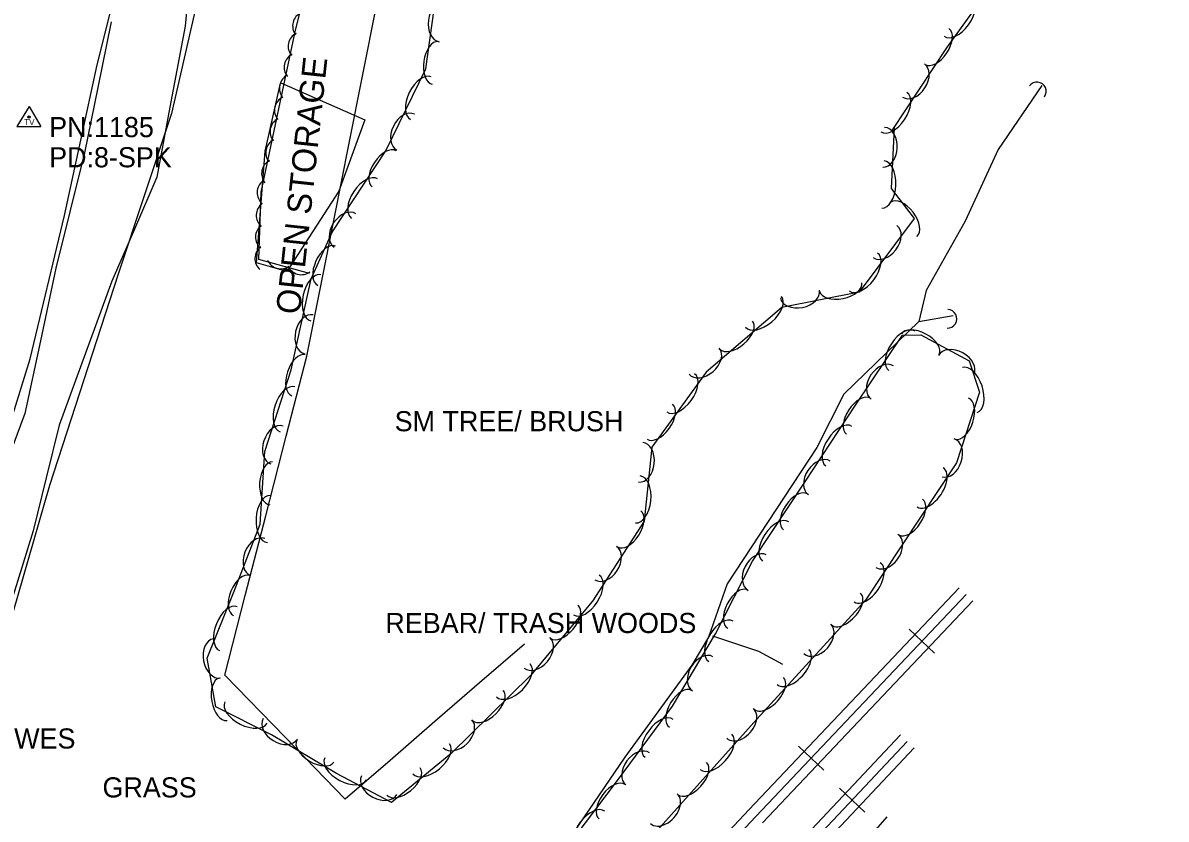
# Model space of a CAD drawing. Extents: x 978516 to 993312, y 1836504 to 1846212.
# Drawn here: x 992595.2 to 992879.3, y 1839818.5 to 1840016.5 of the extents above; entities that cross this region are included whole.
import ezdxf

# ---------------------------------------------------------------- set-up
doc = ezdxf.new("R2010")
doc.units = 0
for name, color, linetype in [('S_CROSS_DRAIN', 7, 'Continuous'), ('S_MISC_BOUNDARY', 7, 'Continuous'), ('S_MISC_BOUNDARY_ANNOT', 7, 'Continuous'), ('S_RAILROAD', 7, 'Continuous'), ('S_SECONDARY_CTL', 7, 'Continuous'), ('S_SECONDARY_CTL_ANNOT', 7, 'Continuous'), ('S_STREAM', 7, 'Continuous'), ('S_SURVEY_TEXT_ANNOT', 7, 'Continuous'), ('S_TREE', 7, 'Continuous')]:
    doc.layers.add(name, color=color, linetype=linetype)

msp = doc.modelspace()

# ---------------------------------------------------------------- linework, layer by layer
at = {"layer": 'S_CROSS_DRAIN'}
for centre, start, end in [((992847.21, 1839999.45), 323.9557, 144.2849), ((992824.97, 1839942.89), 267.6946, 88.0238)]:
    msp.add_arc(centre, 2.3, start, end, dxfattribs=at)
at = {"layer": 'S_MISC_BOUNDARY'}
msp.add_lwpolyline([(992659.34, 1840001.55), (992680.18, 1839992.35), (992673.71, 1839974.64), (992660.8, 1839954.66), (992653.26, 1839956.83), (992655.4, 1839984.6), (992659.23, 1840001.48)], dxfattribs=at)
at = {"layer": 'S_RAILROAD'}
for p, q in [((992815.41, 1839865.73), (992821.71, 1839859.76)), ((992816.84, 1839864.38), (992816.86, 1839864.35)), ((992820.26, 1839861.14), (992820.18, 1839861.21)), ((992787.91, 1839836.68), (992794.21, 1839830.71)), ((992789.34, 1839835.33), (992789.36, 1839835.3)), ((992792.76, 1839832.09), (992792.68, 1839832.16)), ((992804.41, 1839820.28), (992798.09, 1839826.23)), ((992799.55, 1839824.86), (992799.62, 1839824.78)), ((992802.98, 1839821.63), (992802.95, 1839821.65))]:
    msp.add_line(p, q, dxfattribs=at)
for points in [[(992775.58, 1839820.8), (992827.85, 1839876.01)], [(992777.31, 1839819.17), (992829.57, 1839874.38)], [(992779.01, 1839817.56), (992831.27, 1839872.77)], [(992818.54, 1839862.72), (992818.56, 1839862.75)], [(992813.25, 1839839.43), (992728.87, 1839749.66)], [(992814.95, 1839837.83), (992730.57, 1839748.06)], [(992816.68, 1839836.2), (992732.3, 1839746.44)], [(992791.04, 1839833.67), (992791.06, 1839833.69)], [(992801.27, 1839823.28), (992801.25, 1839823.25)], [(992710.17, 1839750.99), (992775.58, 1839820.79)], [(992711.9, 1839749.37), (992777.31, 1839819.17)], [(992786.95, 1839792.55), (992809.98, 1839819.06)]]:
    msp.add_lwpolyline(points, dxfattribs=at)
at = {"layer": 'S_SECONDARY_CTL'}
for p, q in [((992596.73, 1839995.67), (992593.72, 1839990.72)), ((992596.73, 1839995.67), (992599.68, 1839990.72)), ((992593.72, 1839990.72), (992599.68, 1839990.72))]:
    msp.add_line(p, q, dxfattribs=at)
for radius in [0.311, 0.183, 0.103]:
    msp.add_circle((992596.73, 1839993.06), radius, dxfattribs=at)
at = {"layer": 'S_STREAM'}
for points in [[(992585.66, 1839633.57), (992582.47, 1839656.88), (992581.09, 1839678.44), (992579.59, 1839708.35), (992580.52, 1839789.75), (992577.93, 1839804.21), (992573.94, 1839841.11), (992579.03, 1839869.57), (992587.95, 1839904), (992597.03, 1839932.98), (992605.53, 1839968.61), (992613.68, 1840006), (992623.48, 1840045.46), (992631.62, 1840074.59), (992635.44, 1840086.96), (992635.72, 1840092.37)], [(992651.67, 1840085.96), (992648.25, 1840073.37), (992642.51, 1840041.89), (992637.8, 1840018.55), (992632.17, 1839993.93), (992618.87, 1839954), (992601.85, 1839901.44), (992592.62, 1839869.54), (992590.98, 1839853.23), (992591.67, 1839813.28), (992594.91, 1839775.62), (992595.1, 1839733.6), (992594.1, 1839706.5), (992599.5, 1839698.63), (992603.84, 1839691.89), (992604.34, 1839688.87), (992604.17, 1839680.64), (992603.73, 1839671.37), (992608.43, 1839656.96)], [(992637.73, 1840039.02), (992635.55, 1840015.63), (992632.01, 1839996.88), (992628.48, 1839978.14), (992622.91, 1839965.2), (992617.33, 1839952.25), (992610.79, 1839934.36), (992604.24, 1839916.47), (992601, 1839903.33), (992597.76, 1839890.2), (992593.88, 1839877.62), (992590.01, 1839865.05), (992590.5, 1839848.66), (992590.98, 1839832.27), (992590.61, 1839810.56), (992591.88, 1839797.78), (992593.16, 1839785.01), (992593.32, 1839772.45), (992593.48, 1839759.9), (992593.65, 1839747.35), (992593.81, 1839734.79)], [(992617.13, 1840016.71), (992613.83, 1840000.44), (992610.52, 1839984.16), (992606.96, 1839969.83), (992603.4, 1839955.5), (992599.55, 1839937.43), (992595.71, 1839919.36), (992590.79, 1839906.15), (992585.87, 1839892.93), (992582.62, 1839880.21), (992579.38, 1839867.49), (992576.54, 1839850.49), (992573.7, 1839833.49), (992574.41, 1839819.17), (992575.11, 1839804.84), (992576.59, 1839783.82), (992576.98, 1839770.84), (992577.36, 1839757.87), (992578.03, 1839735.89)], [(992848.44, 1840000.93), (992837.53, 1839985.03), (992829.38, 1839967.14), (992819.7, 1839949.97), (992817.86, 1839942.24), (992799.18, 1839924.13), (992792.47, 1839910.93), (992770.18, 1839877.03), (992765.59, 1839863.74), (992761.46, 1839856.77), (992744.79, 1839833.92), (992728.15, 1839809.45), (992712.92, 1839792.12), (992696.24, 1839772.24), (992672.37, 1839748.55), (992644.2, 1839718.39), (992624.5, 1839694.93), (992616.73, 1839693.21), (992605.06, 1839689.67)], [(992817.86, 1839942.24), (992826.4, 1839943.72)], [(992766.58, 1839864.04), (992777.99, 1839860.28), (992783.99, 1839857.05)]]:
    msp.add_lwpolyline(points, dxfattribs=at)
at = {"layer": 'S_TREE'}
for points in [[(992666.45, 1839954.2), (992653.83, 1839957.61), (992654.4, 1839974.41), (992662.91, 1840014.68), (992674.58, 1840060.71), (992681.69, 1840076.17), (992699.76, 1840084.26), (992719.79, 1840095.82), (992736.9, 1840102.87), (992760, 1840103.51), (992773.97, 1840109.49), (992778.22, 1840123.41), (992799.45, 1840117.79), (992835.12, 1840098.17), (992879.3, 1840066.51)], [(992719.84, 1839862.03), (992708.71, 1839852.4), (992697.58, 1839842.76), (992686.45, 1839833.12), (992675.32, 1839823.49), (992660.36, 1839838.87), (992645.39, 1839854.26), (992650.48, 1839874.09), (992655.57, 1839893.92), (992660.66, 1839913.74), (992665.75, 1839933.57), (992669.23, 1839951.09), (992672.72, 1839968.61), (992676.2, 1839986.13), (992679.68, 1840003.64), (992683.16, 1840021.16), (992686.64, 1840038.68), (992690.12, 1840056.2), (992693.6, 1840073.72), (992712, 1840077.09), (992730.4, 1840080.46)], [(992811.72, 1839990.38), (992811, 1839975.3), (992816.66, 1839967.81), (992802.98, 1839949.54), (992783.79, 1839945.74), (992765.01, 1839929.65), (992751.5, 1839910.99), (992749.61, 1839892.62), (992736.74, 1839872.68), (992721.32, 1839854.2), (992701.55, 1839834.77), (992686.78, 1839822.67), (992673.1, 1839829.82), (992657.01, 1839839.46), (992643.17, 1839846.39), (992641.01, 1839858.49), (992647.72, 1839875.16), (992654.16, 1839891.87), (992655.29, 1839909.92), (992661.91, 1839930.18), (992666.88, 1839952.86), (992672.08, 1839964.4), (992685.41, 1839984.69), (992695.33, 1840005.06), (992698.47, 1840027.69)], [(992834.59, 1840024), (992824.7, 1840010.28), (992811.16, 1839989.68)], [(992729.62, 1839810.49), (992742.95, 1839828.13), (992756.59, 1839846.62), (992767.31, 1839864.55), (992776.47, 1839882.62), (992789.72, 1839902.5), (992802.09, 1839921.4), (992813.78, 1839938.86), (992818.38, 1839938.89), (992830.34, 1839932.41), (992832.89, 1839924.7), (992827.21, 1839907.05), (992804.61, 1839872.91), (992777.57, 1839843.38), (992742.97, 1839804.68)]]:
    msp.add_lwpolyline(points, dxfattribs=at)
for centre in [(992657.06, 1839974.28), (992656.83, 1839968.63), (992656.65, 1839963.19), (992656.5, 1839957.89)]:
    msp.add_arc(centre, 3.64, 127.2716, 228.8685, dxfattribs=at)
for centre, major_axis, ratio, start_param, end_param in [((992699.35, 1840016.69), (-0.68, -4.91), 0.685311, 3.141593, 6.283185), ((992827.59, 1840017.91), (3.43, 4.76), 0.55008, 3.141593, 6.283185), ((992665.88, 1840015.71), (-3.63, 0.3), 0.999722, 5.231736, 7.004937), ((992664.77, 1840010.63), (-0.75, -3.56), 0.999994, 3.825788, 5.598989), ((992822.38, 1840010.61), (2.94, 4.47), 0.540711, 3.141593, 6.283185), ((992697.68, 1840006.52), (-0.73, -5.3), 0.540699, 3.141593, 6.283185), ((992663.75, 1840005.45), (-0.75, -3.56), 0.999994, 3.825788, 5.598989), ((992816.51, 1840002.15), (2.72, 4.14), 0.685325, 3.141593, 6.283185), ((992662.58, 1840000.24), (-0.75, -3.56), 0.999994, 3.825788, 5.598989), ((992694.13, 1839997.74), (-2.57, -5.28), 0.55008, 3.141593, 6.283185), ((992811.64, 1839994.27), (3.22, 4.9), 0.550091, 3.141593, 6.283185), ((992661.38, 1839994.72), (-0.75, -3.56), 0.999994, 3.825789, 5.598989), ((992690.31, 1839989.31), (-2.17, -4.45), 0.685311, 3.141593, 6.283185), ((992660.25, 1839989.4), (-0.75, -3.56), 0.999994, 3.825789, 5.598989), ((992809.1, 1839985.54), (0.24, 4.95), 0.685311, 3.141593, 6.283185), ((992659.19, 1839984.2), (-0.75, -3.56), 0.999994, 3.825788, 5.598989), ((992684.98, 1839980.18), (-2.94, -4.47), 0.540699, 3.141593, 6.283185), ((992658.17, 1839979.02), (-0.75, -3.56), 0.999994, 3.825788, 5.598989), ((992808.92, 1839976.28), (0.28, 5.86), 0.55008, 3.141593, 6.283185), ((992680.11, 1839972.76), (-3.22, -4.91), 0.55008, 3.141593, 6.283185), ((992814.12, 1839967.65), (-3.23, 4.26), 0.540699, 3.141593, 6.283185), ((992675.25, 1839964.88), (-2.72, -4.14), 0.685311, 3.141593, 6.283185), ((992809.43, 1839962.12), (2.97, 3.97), 0.685311, 3.141593, 6.283185), ((992670.66, 1839956.09), (-2.2, -4.87), 0.540699, 3.141593, 6.283185), ((992804.08, 1839954.55), (3.52, 4.7), 0.55008, 3.141593, 6.283185), ((992659.28, 1839958.97), (3.52, -0.95), 0.999937, 3.825789, 5.598989), ((992664.41, 1839957.51), (3.52, -0.95), 0.999937, 3.825789, 5.598989), ((992668.02, 1839948.13), (-1.26, -5.73), 0.55008, 3.141593, 6.283185), ((992798.45, 1839950.8), (5.25, 1.04), 0.540699, 3.141593, 6.283185), ((992779.23, 1839944.62), (4.46, 3.82), 0.55008, 3.141593, 6.283185), ((992788.3, 1839949.06), (4.86, 0.96), 0.685311, 3.141593, 6.283185), ((992666.29, 1839939.03), (-1.06, -4.84), 0.685311, 3.141593, 6.283185), ((992772.49, 1839938.85), (4.06, 3.48), 0.540699, 3.141593, 6.283185), ((992813.68, 1839934.92), (-3.26, -4.88), 0.546566, 3.141593, 6.283185), ((992818.2, 1839936.58), (-4.7, 2.55), 0.540585, 3.141593, 6.283185), ((992663.7, 1839928.84), (-1.66, -5.08), 0.540699, 3.141593, 6.283185), ((992764.5, 1839932.35), (3.76, 3.22), 0.685311, 3.141593, 6.283185), ((992827.13, 1839931.44), (-4.36, 2.36), 0.685166, 3.141593, 6.283185), ((992808.75, 1839927.08), (-2.76, -4.12), 0.680933, 3.141593, 6.283185), ((992830.5, 1839925.2), (-1.84, 5.57), 0.54903, 3.141593, 6.283185), ((992758.66, 1839924.5), (3.44, 4.75), 0.55008, 3.141593, 6.283185), ((992660.95, 1839920.41), (-1.82, -5.58), 0.55008, 3.141593, 6.283185), ((992802.83, 1839918.67), (-2.93, -4.47), 0.537252, 3.141593, 6.283185), ((992828.54, 1839918.07), (1.64, 5.09), 0.537662, 3.141593, 6.283185), ((992753.46, 1839917.32), (3.14, 4.33), 0.540699, 3.141593, 6.283185), ((992658.32, 1839911.53), (-1.54, -4.71), 0.685311, 3.141593, 6.283185), ((992797.97, 1839911.25), (-3.22, -4.91), 0.546573, 3.141593, 6.283185), ((992748.72, 1839907.23), (0.51, 4.93), 0.685311, 3.141593, 6.283185), ((992825.14, 1839908.34), (1.52, 4.72), 0.681461, 3.141593, 6.283185), ((992793.11, 1839903.36), (-2.71, -4.15), 0.680942, 3.141593, 6.283185), ((992656.92, 1839901.97), (-0.33, -5.34), 0.540699, 3.141593, 6.283185), ((992820.68, 1839901), (3.25, 4.86), 0.548517, 3.14919, 6.290783), ((992748.03, 1839897.99), (0.6, 5.84), 0.55008, 3.141593, 6.283185), ((992787.19, 1839894.91), (-2.96, -4.45), 0.537247, 3.141593, 6.283185), ((992656.37, 1839893.12), (-0.36, -5.86), 0.55008, 3.141593, 6.283185), ((992815.8, 1839893.63), (2.96, 4.43), 0.539164, 3.148954, 6.290546), ((992745.83, 1839890.67), (2.9, 4.49), 0.540699, 3.141593, 6.283185), ((992782.27, 1839887.53), (-3.25, -4.88), 0.546568, 3.141593, 6.283185), ((992653.55, 1839883.67), (-1.78, -4.62), 0.685311, 3.141593, 6.283185), ((992809.92, 1839885.21), (2.76, 4.09), 0.683335, 3.154007, 6.2956), ((992740.02, 1839882.16), (2.69, 4.16), 0.685311, 3.141593, 6.283185), ((992777.7, 1839879.8), (-2.24, -4.42), 0.681087, 3.141593, 6.283185), ((992805.04, 1839877.38), (3.25, 4.86), 0.548517, 3.14919, 6.290783), ((992649.58, 1839874.12), (-2, -4.96), 0.540699, 3.141593, 6.283185), ((992735.22, 1839874.23), (3.18, 4.93), 0.55008, 3.141593, 6.283185), ((992772.81, 1839870.73), (-2.42, -4.77), 0.537367, 3.141593, 6.283185), ((992799.77, 1839870.74), (3.61, 3.94), 0.537239, 3.141187, 6.28278), ((992646.27, 1839865.89), (-2.19, -5.44), 0.55008, 3.141593, 6.283185), ((992729.74, 1839867.6), (3.43, 4.1), 0.540699, 3.141593, 6.283185), ((992768.67, 1839862.72), (-3.01, -5.04), 0.546607, 3.141593, 6.283185), ((992792.62, 1839863.32), (3.34, 3.66), 0.680925, 3.140911, 6.282503), ((992643.43, 1839858.49), (0.87, -4.88), 0.685311, 3.141593, 6.283185), ((992722.93, 1839859.86), (3.18, 3.8), 0.685311, 3.141593, 6.283185), ((992764.15, 1839854.64), (-2.54, -4.25), 0.680984, 3.141593, 6.283185), ((992786.56, 1839856.31), (3.96, 4.33), 0.546559, 3.141174, 6.282767), ((992717.06, 1839852.99), (4.19, 4.11), 0.55008, 3.141593, 6.283185), ((992644.99, 1839848.3), (0.94, -5.26), 0.540699, 3.141593, 6.283185), ((992758.64, 1839845.93), (-2.74, -4.59), 0.537285, 3.141593, 6.283185), ((992780.57, 1839849.77), (3.61, 3.94), 0.537239, 3.141187, 6.28278), ((992710.74, 1839846.78), (3.81, 3.75), 0.540699, 3.141593, 6.283185), ((992650.66, 1839845.02), (5.25, -2.63), 0.55008, 3.141593, 6.283185), ((992773.43, 1839842.3), (3.31, 3.69), 0.680934, 3.142798, 6.284391), ((992659.17, 1839840.94), (4.25, -2.55), 0.685311, 3.141593, 6.283185), ((992703.21, 1839839.74), (3.53, 3.47), 0.685311, 3.141593, 6.283185), ((992753.3, 1839838.6), (-3.48, -4.72), 0.546545, 3.141593, 6.283185), ((992667.88, 1839835.43), (4.59, -2.75), 0.540699, 3.141593, 6.283185), ((992696.65, 1839833.5), (4.54, 3.72), 0.55008, 3.141593, 6.283185), ((992767.45, 1839835.22), (3.91, 4.37), 0.546567, 3.142333, 6.283925), ((992748.01, 1839830.99), (-2.94, -3.99), 0.680907, 3.141593, 6.283185), ((992675.42, 1839831), (5.2, -2.72), 0.55008, 3.141593, 6.283185), ((992761.54, 1839828.61), (3.57, 3.98), 0.537246, 3.14231, 6.283902), ((992683.75, 1839826.95), (4.39, -2.3), 0.685311, 3.141593, 6.283185), ((992689.79, 1839827.88), (4.13, 3.39), 0.540699, 3.141593, 6.283185), ((992741.62, 1839822.87), (-3.22, -4.27), 0.537222, 3.141593, 6.283185), ((992754.48, 1839821.1), (3.31, 3.69), 0.680934, 3.142798, 6.284391), ((992736.27, 1839815.8), (-3.54, -4.68), 0.546542, 3.141593, 6.283185)]:
    msp.add_ellipse(centre, major_axis=major_axis, ratio=ratio, start_param=start_param, end_param=end_param, dxfattribs=at)

# ---------------------------------------------------------------- texts
at = {"layer": 'S_MISC_BOUNDARY_ANNOT'}
msp.add_text('OPEN STORAGE', height=6.0006, rotation=83.8647, dxfattribs=at).set_placement((992664.03, 1839943.82))
at = {"layer": 'S_SECONDARY_CTL'}
msp.add_text('TV', height=1.5, dxfattribs=at).set_placement((992595.53, 1839991.05))
at = {"layer": 'S_SECONDARY_CTL_ANNOT'}
for s, p in [('PN:1185', (992601.73, 1839988.06)), ('PD:8-SPK', (992601.73, 1839980.56))]:
    msp.add_text(s, height=5, dxfattribs=at).set_placement(p)
at = {"layer": 'S_SURVEY_TEXT_ANNOT'}
for s, p in [('SM TREE/ BRUSH', (992687.59, 1839914.94)), ('REBAR/ TRASH WOODS', (992685.28, 1839864.77)), ('POINT ON ROAD UNDER LOWES', (992503.14, 1839836.06)), ('GRASS', (992614.99, 1839823.9))]:
    msp.add_text(s, height=5, dxfattribs=at).set_placement(p)

doc.saveas('drawing.dxf')
